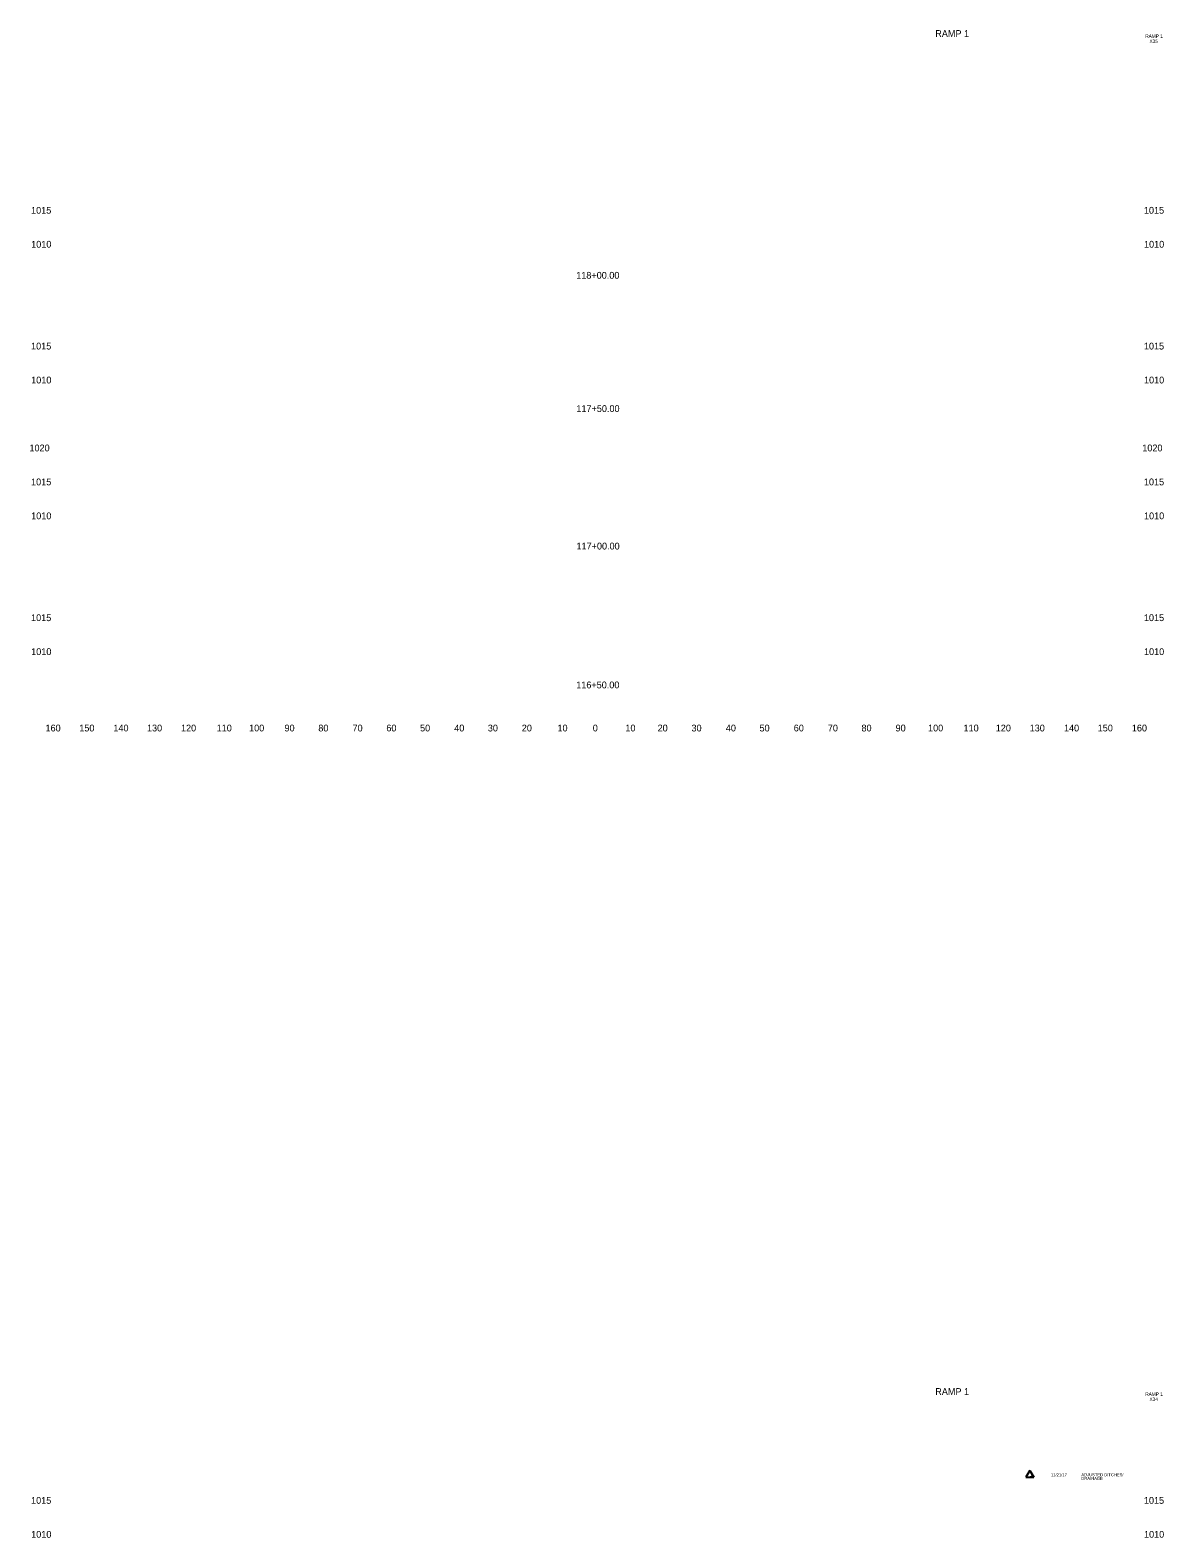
# Model space of a CAD drawing. Extents: x 4994 to 7869, y 4997 to 8804.
# Drawn here: x 6538.6 to 6872.5, y 6360 to 6804.1 of the extents above; entities that cross this region are included whole.
import ezdxf

# ---------------------------------------------------------------- set-up
doc = ezdxf.new("R2010")
doc.units = 0
for name, color, linetype in [('RD_SHT_ID', 7, 'Continuous'), ('RD_SHT_TX', 7, 'Continuous'), ('RD_XS_TX_Offset', 7, 'Continuous'), ('RD_XS_TX_Station', 7, 'Continuous')]:
    doc.layers.add(name, color=color, linetype=linetype)

msp = doc.modelspace()

# ---------------------------------------------------------------- linework, layer by layer
at = {"layer": 'RD_SHT_TX'}
for p, q in [((6833.05, 6379.83), (6831.91, 6377.8)), ((6831.91, 6377.8), (6834.19, 6377.8)), ((6833.05, 6379.83), (6834.19, 6377.8))]:
    msp.add_line(p, q, dxfattribs=at)

# ---------------------------------------------------------------- texts
at = {"layer": 'RD_SHT_ID'}
for s, height, p in [('RAMP 1', 2, (6805.19, 6802.06)), ('RAMP 1', 1, (6867.06, 6801.8)), ('X35', 1, (6868.29, 6800.3)), ('RAMP 1', 2, (6805.19, 6402.06)), ('RAMP 1', 1, (6867.06, 6401.8)), ('X34', 1, (6868.29, 6400.3))]:
    msp.add_text(s, height=height, dxfattribs=at).set_placement(p)
at = {"layer": 'RD_SHT_TX'}
for s, p in [('1', (6833.05, 6378.13)), ('11/21/17', (6839.24, 6378.09)), ('ADJUSTED DITCHES/', (6848.22, 6378.12)), ('DRAINAGE', (6848.22, 6377.02))]:
    msp.add_text(s, height=0.88, dxfattribs=at).set_placement(p)
at = {"layer": 'RD_XS_TX_Offset'}
for s, p in [('1015', (6538.85, 6750)), ('1015', (6866.65, 6750)), ('1010', (6538.88, 6740)), ('1010', (6866.68, 6740)), ('1015', (6538.85, 6710)), ('1015', (6866.65, 6710)), ('1010', (6538.88, 6700)), ('1010', (6866.68, 6700)), ('1020', (6538.37, 6680)), ('1020', (6866.17, 6680)), ('1015', (6538.85, 6670)), ('1015', (6866.65, 6670)), ('1010', (6538.88, 6660)), ('1010', (6866.68, 6660)), ('1015', (6538.85, 6630)), ('1015', (6866.65, 6630)), ('1010', (6538.88, 6620)), ('1010', (6866.68, 6620)), ('160', (6543.1, 6597.5)), ('150', (6553.04, 6597.5)), ('140', (6563.1, 6597.5)), ('130', (6572.99, 6597.5)), ('120', (6583.01, 6597.5)), ('110', (6593.51, 6597.5)), ('100', (6603.07, 6597.5)), ('90', (6613.5, 6597.5)), ('80', (6623.46, 6597.5)), ('70', (6633.54, 6597.5)), ('60', (6643.5, 6597.5)), ('50', (6653.43, 6597.5)), ('40', (6663.5, 6597.5)), ('30', (6673.39, 6597.5)), ('20', (6683.4, 6597.5)), ('10', (6693.91, 6597.5)), ('0', (6704.3, 6597.5)), ('0', (6704.3, 6597.5)), ('10', (6713.91, 6597.5)), ('20', (6723.4, 6597.5)), ('30', (6733.39, 6597.5)), ('40', (6743.5, 6597.5)), ('50', (6753.43, 6597.5)), ('60', (6763.5, 6597.5)), ('70', (6773.54, 6597.5)), ('80', (6783.46, 6597.5)), ('90', (6793.5, 6597.5)), ('100', (6803.07, 6597.5)), ('110', (6813.51, 6597.5)), ('120', (6823.01, 6597.5)), ('130', (6832.99, 6597.5)), ('140', (6843.1, 6597.5)), ('150', (6853.04, 6597.5)), ('160', (6863.1, 6597.5)), ('1015', (6538.85, 6370)), ('1015', (6866.65, 6370)), ('1010', (6538.88, 6360)), ('1010', (6866.68, 6360))]:
    msp.add_text(s, height=2, dxfattribs=at).set_placement(p)
at = {"layer": 'RD_XS_TX_Station'}
for s, p in [('118+00.00', (6699.43, 6730.85)), ('117+50.00', (6699.48, 6691.6)), ('117+00.00', (6699.51, 6651.09)), ('116+50.00', (6699.43, 6610.2))]:
    msp.add_text(s, height=2, dxfattribs=at).set_placement(p)

doc.saveas('drawing.dxf')
